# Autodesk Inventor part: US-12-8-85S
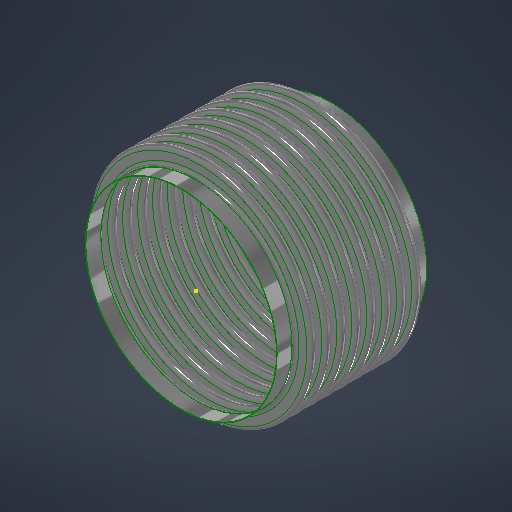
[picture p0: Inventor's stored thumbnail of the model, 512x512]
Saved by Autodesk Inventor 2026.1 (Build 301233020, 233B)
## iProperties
Category: 20 GA (0.036 THICK)
RuleStatus: InUse
Created: 2026-07
Part Number: US-12-8-85S
Project: =STOCK BELLOWS: <Stock Number><SFILL>
Material: ASTM A240-304
Description: =STOCK BELLOWS: <Stock Number>, <SID_> I.D., <SOD_> O.D., <SPLY_> PLY, <Category>, <SNET_CONS> CONS.<PITCH_><STANGENT_> TANGENT<SFILL>
Document SubType Name: Sheet Metal
Designer: LC
Stock Number: U.S-12-8-85S
Surface Area: 659.127 cm^2
Volume: 56.61 cm^3
Sheet Metal Rule: Default
Appearance: STAINLESS STEEL
NET_TUBE: 3.428
COUNTER: 1.500
PBAR: 1.214
PSET: 5.356
PLY: 2
CONS: 2
THK: 0.036
ID: 4.500
OD: 5.500
CONS_: 2
TANGENT: 0.500
PITCH: 0.375
BELLOWS_UPSET: 0.000
NET_CONS: 2
S_CONS: 0
Description_Units: 0
ID_M: 114.30 mm
OD_M: 139.70 mm
THK_M: 0.91 mm
ID_U: 4.500 in
OD_U: 5.500 in
THK_U: 0.036 in
TANGENT2: 0.500
d79: 1.000
d82: 1.000
d83: 26.000
d84: 24.000
d80: 2.571
d81: 10
SID: 2.375
SCONS_: 8
SPITCH: 0.250
SBELLOWS_UPSET: 0.000
SNET_CONS: 8
SS_CONS: 0
SCONS: 8
d174: 8
d177: 0.018
d178: 2.375
d179: 3.000
d180: 0.375
d181: 1.000
d182: 0.000
d190: 8
d191: 1
d192: 1
d193: 8
d194: 0
PART_NUMBER: U.S-12-8-85S
PRESSURE: 85
SIZE: 12.00
STANGENT_: 1.000
d214: 8
d217: 0.030
d218: 6.625
d219: 8.125
d220: 0.500
d221: 1.000
d222: 0.000
d230: 8
d231: 1
d232: 1
d233: 8
d234: 0
STANGENT: 4.000
SPLY_: 1
STHK_: 0.036
SID_: 12.750
SOD_: 14.875
SPITCH_: 1.000
STANGENT__: 1.000
SBELLOWS_UPSET_: 0.000
SDIFF_TAN: 1.000
TAN_TO_TAN: 0.750 in
d252: 2
d275: 2
d287: 0.050
d289: 0.500
d290: 0.000
d263: 2
d265: 1
d268: 2
d269: 0
d286: 2
d288: 1
d291: 2
d292: 0
SOD_NECK: 12 13/16
CFILL: .
SFILL: .
PITCH_: =, <SPITCH_> PITCH,
SREROLL: 0.750
MATTABLE: 20 GA (0.036 THICK)
MESH: ,
CSECT: 2
Author: LC
Keywords: 20 GA (0.036 THICK)
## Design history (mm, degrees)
sketch "Sketch2"
  geometry: L1 (0, -183.595)-(0, 600.956) reference; L2 (58.979, 0)-(57.15, 0); L3 (60.446, -1.467)-(66.554, -1.467); L4 (60.446, -3.296)-(66.554, -3.296); L5 (66.554, -8.058)-(60.446, -8.058); L6 (66.554, -6.229)-(60.446, -6.229); L7 (58.979, -9.525)-(57.15, -9.525); L8 (60.446, 0)-(60.446, -9.525); L9 (66.554, -4.762)-(69.85, -4.763); L10 (57.15, 0)-(57.15, -9.525); L11 (20.376, 102.841)-(20.376, 101.926); L12 (58.262, 488.877)-(58.262, 349.177); L13 (58.262, 479.352)-(58.262, 339.652); L14 (93.133, -58.817)-(93.133, -71.517); L15 (118.746, -66.401)-(118.746, -66.401); L16 (66.554, -6.229)-(66.554, -8.058); L17 (60.446, -6.229)-(60.446, -8.058); L18 (60.446, -7.144)-(66.554, -7.144); L19 (69.85, 0)-(69.85, -9.525); L20 (-66.554, -6.229)-(-66.554, -8.058); L21 (-66.554, -1.467)-(-60.446, -1.467); L22 (-66.554, -3.296)-(-60.446, -3.296); L23 (-60.446, -6.229)-(-66.554, -6.229); L24 (-66.554, -7.144)-(-60.446, -7.144); L25 (-60.446, -8.058)-(-66.554, -8.058); L26 (-60.446, -6.229)-(-60.446, -8.058); L27 (-57.15, -2.522)-(-57.15, -12.047); L28 (-60.446, -4.763)-(-57.15, -4.763); L29 (-66.554, 3.828)-(-66.554, -9.525); L30 (-68.021, 0)-(-69.85, 0); L31 (-69.85, 0)-(-69.85, -9.525); L32 (-68.021, -9.525)-(-69.85, -9.525); A1 r 1.467 centre (60.446, 0) between (58.979, 0) and (60.446, -1.467); A2 r 3.296 centre (60.446, 0) between (57.15, 0) and (60.446, -3.296); A3 r 3.296 centre (66.554, -4.762) between (66.554, -8.058) and (66.554, -1.467); A4 r 1.467 centre (66.554, -4.762) between (66.554, -6.229) and (66.554, -3.296); A5 r 1.467 centre (60.446, -9.525) between (60.446, -8.058) and (58.979, -9.525); A6 r 3.296 centre (60.446, -9.525) between (60.446, -6.229) and (57.15, -9.525); A7 r 2.381 centre (66.554, -4.762) between (66.554, -7.144) and (68.936, -4.762); A8 r 2.381 centre (60.446, -9.525) between (60.446, -7.144) and (58.064, -9.525); A9 r 1.467 centre (-66.554, -9.525) between (-66.554, -8.058) and (-68.021, -9.525); A10 r 1.467 centre (-60.446, -4.763) between (-60.446, -6.229) and (-60.446, -3.296); A11 r 2.381 centre (-60.446, -4.763) between (-60.446, -7.144) and (-58.064, -4.763); A12 r 3.296 centre (-60.446, -4.763) between (-60.446, -8.058) and (-60.446, -1.467); A13 r 2.381 centre (-66.554, -9.525) between (-66.554, -7.144) and (-68.936, -9.525); A14 r 3.296 centre (-66.554, -9.525) between (-66.554, -6.229) and (-69.85, -9.525); A15 r 1.467 centre (-66.554, 0) between (-68.021, 0) and (-66.554, -1.467); A16 r 3.296 centre (-66.554, 0) between (-69.85, 0) and (-66.554, -3.296); 10 further points
  constraints: 62 end point, 38 point on circle, 20 tangent, 16 centre point, 12 parallel, 9 midpoint, 7 vertical, 6 coincident, 6 concentric, 6 point on line, 4 equal radius, 4 perpendicular, 3 horizontal, 1 collinear, 1 horizontal alignment, 10 other
  dimensions: "THK" = 0.9144 distance of L11.start L11.end; "ID" = 114.3 distance of L11.end point (20.376, -12.374); "OD" = 139.7 distance of L12.start L12.end; "PITCH" = 9.525 distance of L12.start L13.start; "TANGENT" = 12.7 distance of L14.start L14.end; "BELLOWS_UPSET" = 0 distance of L15.start L15.end; "d43" = 114.3 diameter of L10 L1 (= ID); "d44" = 139.7 diameter of L9.end L1 (= OD); "d45" = 1.8288 distance between parallel lines of L5 L6 (computed from THK, PLY); "d46" = 3.29565 radius of A3 (computed from PITCH, THK, PLY); "UPSET_PITCH" = 9.525 distance of L2.end L7.end (derived); "SIDEWALL_ANGLE" = 0 deg angle of L3 L9 (derived); "CON_GAP" = 2.9337 distance of point (60.446, -6.229) point (60.446, -3.296) (derived); "TAN1" = 3.74046 dimension on A8 (derived); "TAN2" = 3.74046 dimension on A7 (derived); "LEG1" = 6.1087 distance of L18.start L18.end (derived); "d278" = 1.8288 distance between parallel lines of L25 L23 (derived); "d279" = 3.29565 radius of A12 (derived); "d280" = 9.525 distance of L30.end L31.end (derived); "d281" = 360 deg dimension on L21 L28 (derived); "d282" = 2.9337 distance of point (-66.554, -6.229) point (-66.554, -3.296) (derived); "d283" = 3.74046 dimension on A13 (derived); "d284" = 3.74046 dimension on A11 (derived); "d285" = 6.1087 distance of L24.start L24.end (derived); "d293" = 114.3 diameter of L27 L1 (derived); "d294" = 139.7 diameter of L31 L1 (derived)
  node "Sketch Rectangular Pattern1" dims "d31" = 25.4, "ID" = 114.3
  node "Sketch Rectangular Pattern2" dims "d39" = 25.4, "PITCH" = 9.525
revolve "CONS" stored, may be unused: angle "d48" = 90 deg
node "BELLOW MIDPLANE"
pattern_linear "Rectangular Pattern2" dims "d52" = 9.525 (= UPSET_PITCH)
sketch "Sketch5"
  geometry: C1 r 58.979 at (0, 0) reference; C2 r 57.15 at (0, 0) reference
extrude "TANGENT" new body sketch "Sketch5" distance "d53" = 12.7 (= TANGENT); taper "d54" = 0 deg
revolve "SAMETAN" stored, may be unused: angle "d65" = 90 deg
revolve "DIFFTAN" stored, may be unused: angle "d70" = 90 deg
sketch "Sketch9"
  geometry: L1 (58.391, 0)-(-58.391, 0) reference; L2 (0, -17.78)-(0, 17.78) reference; L3 (41.708, 0)-(-41.708, 0); L4 (41.708, -11.906)-(41.708, 11.906); L5 (29.008, -11.906)-(29.008, 11.906); L6 (15.418, 11.906)-(15.418, -11.906); L7 (-29.008, -11.906)-(-29.008, 11.906); L8 (-41.708, -11.906)-(-41.708, 11.906); L9 (40.914, -11.906)-(40.914, 11.906); L10 (41.708, -11.906)-(40.914, -11.906); L11 (41.708, 11.906)-(40.914, 11.906); L12 (15.815, 11.906)-(15.022, 11.906); L13 (15.022, 11.906)-(15.022, -11.906); L14 (15.022, -11.906)-(15.815, -11.906); L15 (15.815, -11.906)-(15.815, 11.906); L16 (-15.815, 11.906)-(-15.815, -11.906); L17 (-15.418, 11.906)-(-15.418, -11.906); L18 (-15.815, -11.906)-(-15.022, -11.906); L19 (-15.022, -11.906)-(-15.022, 11.906); L20 (-15.022, 11.906)-(-15.815, 11.906); L21 (-41.708, -11.906)-(-40.914, -11.906); L22 (-40.914, -11.906)-(-40.914, 11.906); L23 (-40.914, 11.906)-(-41.708, 11.906); L24 (-41.708, 11.906)-(-41.708, -11.906); L25 (41.708, -0.397)-(-41.708, -0.397); L26 (-41.708, -0.397)-(-41.708, 0.397); L27 (-41.708, 0.397)-(41.708, 0.397); L28 (41.708, 0.397)-(41.708, -0.397); L29 (-41.708, 11.906)-(41.708, 11.906); L30 (41.708, 11.906)-(41.708, 12.7); L31 (41.708, 12.7)-(-41.708, 12.7); L32 (-41.708, 12.7)-(-41.708, 11.906); L33 (41.708, -11.906)-(-41.708, -11.906); L34 (-41.708, -11.906)-(-41.708, -12.7); L35 (-41.708, -12.7)-(41.708, -12.7); L36 (41.708, -12.7)-(41.708, -11.906); 30 further points
  constraints: 68 end point, 13 midpoint, 13 parallel, 8 horizontal, 7 perpendicular, 6 equal length, 3 point on line, 2 vertical, 14 other
  dimensions: "d115" = 23.8125 distance of L4.start L4.end (derived); "d116" = 12.7 distance between parallel lines of L4 L5 (derived); "d117" = 13.58962 distance between parallel lines of L5 L6 (derived); "d125" = 44.42645 distance between parallel lines of L7 L6 (derived); "d127" = 12.7 distance between parallel lines of L8 L7 (derived); "d128" = 26.28962 distance between parallel lines of L6 L4 (derived); "d130" = 83.41607 distance between parallel lines of L8 L4 (derived); "RULER_THK" = 0.79375 distance between parallel lines of L4 L9; "d135" = 0.79375 distance of L13.end L14.end (derived); "d138" = 30.83684 distance of L13.end L16.end (derived); "d143" = 0.79375 distance of L22.end L8.end (derived); "d144" = 0.79375 distance between parallel lines of L27 L25 (derived)
extrude "RULER" join sketch "Sketch9" distance "d149" = 0.79375 (derived); taper "d150" = 0 deg
extrude "BARS" join sketch "Sketch9" distance "d151" = 0.79375 (derived); taper "d152" = 0 deg
pattern_linear "Rectangular Pattern4" dims "d155" = 30.83684 (derived)
sketch "Sketch13"
  geometry: L1 (93.149, -52.467)-(93.149, -77.867); L2 (162.839, 0)-(161.925, 0); L3 (162.839, -25.4)-(161.925, -25.4); L4 (182.105, -19.507)-(168.732, -19.507); L5 (182.105, -18.593)-(168.732, -18.593); L6 (182.105, -12.7)-(188.912, -12.7); L7 (168.732, -5.893)-(182.105, -5.893); L8 (168.732, 0)-(168.732, -25.4); L9 (161.925, 0)-(161.925, -25.4); L10 (58.254, -267.831)-(58.254, -645.656); L11 (58.254, -293.231)-(58.254, -671.056); L12 (58.254, -344.031)-(58.254, -721.856); L13 (58.254, -369.431)-(58.254, -747.256); L14 (58.254, -394.831)-(58.254, -772.656); L15 (58.254, -420.231)-(58.254, -798.056); L16 (58.254, -445.631)-(58.254, -823.456); L17 (58.254, -318.631)-(58.254, -696.456); L18 (20.376, 102.841)-(20.376, 101.926); L19 (168.732, -6.807)-(182.105, -6.807); L20 (0, -960.455)-(0, 280.056) reference; L21 (-31.75, 0)-(190.5, 0) reference; A1 r 5.893 centre (168.732, 0) between (162.839, 0) and (168.732, -5.893); A2 r 5.893 centre (168.732, -25.4) between (168.732, -19.507) and (162.839, -25.4); A3 r 6.807 centre (168.732, -25.4) between (168.732, -18.593) and (161.925, -25.4); A4 r 5.893 centre (182.105, -12.7) between (182.105, -18.593) and (182.105, -6.807); A5 r 6.807 centre (182.105, -12.7) between (182.105, -19.507) and (182.105, -5.893); A6 r 6.807 centre (168.732, 0) between (161.925, 0) and (168.732, -6.807); 6 further points; 1 other entity
  constraints: 38 end point, 15 point on circle, 9 tangent, 6 centre point, 6 parallel, 5 vertical alignment, 4 point on line, 4 vertical, 3 coincident, 3 concentric, 2 collinear, 2 equal radius, 1 horizontal, 1 perpendicular, 23 other
  dimensions: "SBELLOWS_UPSET_" = 0 distance of point (118.762, -66.401) point (118.762, -66.401); "STOTAL_THK_BELLOW__" = 0.9144 distance between parallel lines of L4 L5 (derived); "d224" = 6.8072 radius of A5 (derived); "d225" = 25.4 distance of L2.end L3.end (derived); "SSIDEWALL_ANGLE_" = 0 deg angle of L7 L6 (derived); "SSCON_GAP_" = 11.7856 distance of point (168.732, -18.593) point (168.732, -6.807) (derived); "d235" = 323.85 diameter of L9 L20 (derived); "d236" = 377.825 diameter of L6.end L20 (derived)
  node "Sketch Rectangular Pattern4" dims "d228" = 25.4
  node "Sketch Rectangular Pattern5" dims "d229" = 25.4
revolve "SBELLOW" stored, may be unused: angle "d197" = 90 deg
pattern_linear "Rectangular Pattern5" dims "d204" = 25.4 (derived)
revolve "STANGENT" stored, may be unused: angle "d240" = 90 deg
revolve "SSAMETAN" stored, may be unused: angle "d241" = 90 deg
revolve "SDIFFTAN" stored, may be unused: angle "d246" = 90 deg
revolve "INVCON" stored, may be unused: angle "d295" = 90 deg
pattern_linear "Rectangular Pattern6" dims "d298" = 9.525 (derived)
revolve "INVTANGENT" stored, may be unused: angle "d302" = 90 deg
revolve "INVSAMETAN" stored, may be unused: angle "d307" = 90 deg
revolve "INVDIFFTAN" stored, may be unused: angle "d312" = 90 deg
sketch "ID BELLOW MOUNT CALC"
  geometry: L1 (44.45, 0)-(38.1, 0); L2 (38.1, 0)-(38.1, 12.7); L3 (38.1, 12.7)-(44.45, 12.7); L4 (44.45, 12.7)-(44.45, 0); L5 (36.513, 12.7)-(34.684, 12.7); L6 (34.684, 12.7)-(34.684, 0); L7 (34.684, 0)-(36.513, 0); L8 (36.513, 0)-(36.513, 12.7); L9 (0, -2.54)-(0, 15.24) reference; L10 (-8.89, 0)-(53.34, 0) reference; 1 further point
  constraints: 16 end point, 5 parallel, 2 collinear, 2 horizontal, 2 perpendicular
  dimensions: "d314" = 12.7 distance of L5.end L6.end (derived); "d315" = 1.8288 distance of L5.start L5.end (derived); "IG" = 1.5875 distance between parallel lines of L2 L8; "PIPE_OD" = 88.9 diameter of L4 L9; "PIPE_WALL" = 6.35 distance of L2.end L3.end; "ID_MT_BELLOW" = 69.3674 diameter of L6 L9 (derived)
revolve "CFILL" stored, may be unused: angle "d320" = 90 deg
pattern_linear "Rectangular Pattern7" dims "d323" = 9.525 (derived)
revolve "SFILL" stored, may be unused: angle "d324" = 90 deg
pattern_linear "Rectangular Pattern8" dims "d327" = 25.4 (derived)
node "STOCK BELLOW MIDPLANE"
sketch "Sketch21"
  geometry: L1 (0, -100.013)-(0, 100.013) reference; L2 (-100.013, 0)-(100.013, 0) reference; L3 (-0.099, 71.437)-(0.099, 71.437); L4 (0.099, 71.437)-(0.099, 55.562); L5 (0.099, 55.562)-(-0.099, 55.562); L6 (-0.099, 55.562)-(-0.099, 71.437); C1 r 55.562 at (0, 0); C2 r 71.437 at (0, 0); 3 further points
  constraints: 8 end point, 2 centre point, 2 coincident, 2 parallel, 2 tangent, 1 horizontal, 1 perpendicular, 1 other
  dimensions: "d329" = 111.125 diameter of C1 (derived); "d330" = 142.875 diameter of C2 (derived); "d331" = 0.19844 distance of L3.start L3.end
extrude "CLAMSHELL" cut sketch "Sketch21" extent not by distance; stored distance "d332" = 0; taper "d333" = 0 deg
pattern_circular "Circular Pattern1" dims angle "d335" = 180 deg (derived)
node "BELLOW"
sketch "Sketch6"
  geometry: L1 (-19.05, 58.979)-(-6.35, 58.979); L2 (-6.35, 58.979)-(-6.35, 57.15); L3 (-6.35, 57.15)-(-19.05, 57.15); L4 (-19.05, 57.15)-(-19.05, 58.979); L5 (2.54, 0)-(-59.69, 0) reference; L6 (-38.1, -108.388)-(-38.1, 156.601) reference; 1 further point
  constraints: 8 end point, 2 parallel, 1 horizontal, 1 perpendicular
  dimensions: "d61" = 12.7 distance of L2.end L3.end (derived); "d62" = 1.8288 distance of L1.end L2.end (derived); "d63" = 114.3 diameter of L3 L5 (derived); "d64" = 19.05 distance between parallel lines of L4 L6 (derived)
sketch "Sketch12"
  geometry: 1 further point
sketch "Sketch14"
  geometry: L1 (-25.4, 162.839)-(0, 162.839); L2 (0, 162.839)-(0, 161.925); L3 (0, 161.925)-(-25.4, 161.925); L4 (-25.4, 161.925)-(-25.4, 162.839); L5 (5.08, 0)-(-30.48, 0) reference; L6 (0, -27.488)-(0, 164.927) reference; 1 further point
  constraints: 8 end point, 2 parallel, 1 collinear, 1 horizontal, 1 perpendicular
  dimensions: "d237" = 0.9144 distance of L3.end L1.start (derived); "d238" = 323.85 diameter of L3 L5 (derived); "d239" = 25.4 distance of L1.start L1.end (derived); "SOD_NECK" = 325.6788 diameter of L1 L5 (derived)
sketch "Sketch15"
  geometry: L1 (-27.488, 0)-(164.927, 0) reference; L2 (161.925, -203.2)-(162.839, -203.2); L3 (162.839, -203.2)-(162.839, -228.6); L4 (162.839, -228.6)-(161.925, -228.6); L5 (161.925, -228.6)-(161.925, -203.2); L6 (0, -276.86)-(0, 60.96) reference; 1 further point
  constraints: 8 end point, 2 parallel, 1 horizontal, 1 perpendicular
  dimensions: "d205" = 25.4 distance of L4.end L2.start (derived); "d206" = 0.9144 distance of L3.end L4.end (derived); "d207" = 323.85 diameter of L5 L6 (derived); "d208" = 203.2 distance between parallel lines of L1 L2 (derived)
node "TANGENT_"
node "SAME_TAN"
sketch "Sketch8"
  geometry: L1 (58.979, -19.05)-(57.15, -19.05); L2 (57.15, -19.05)-(57.15, -31.75); L3 (57.15, -31.75)-(58.979, -31.75); L4 (58.979, -31.75)-(58.979, -19.05); L5 (0, -40.64)-(0, 21.59) reference; L6 (-108.388, 0)-(156.601, 0) reference; 1 further point
  constraints: 8 end point, 2 parallel, 1 horizontal, 1 perpendicular
  dimensions: "d66" = 114.3 diameter of L2 L5 (derived); "TOTAL_THK_BELLOW" = 1.8288 distance of L2.end L3.end (derived); "d68" = 19.05 distance between parallel lines of L1 L6 (derived); "d69" = 12.7 distance of L1.end L2.end (derived)
node "DIFF_TAN"
node "Sketch Rectangular Pattern3" dims "d138" = 30.83684 (derived), "d141" = 25.4
node "SBELLOW_"
node "STANGENT_"
node "SSAME_TAN"
sketch "Sketch16"
  geometry: L1 (162.839, -203.2)-(161.925, -203.2); L2 (161.925, -203.2)-(161.925, -228.6); L3 (161.925, -228.6)-(162.839, -228.6); L4 (162.839, -228.6)-(162.839, -203.2); L5 (0, -276.86)-(0, 60.96) reference; L6 (-27.488, 0)-(164.927, 0) reference; 1 further point
  constraints: 8 end point, 2 parallel, 1 horizontal, 1 perpendicular
  dimensions: "SDIFF_TAN" = 25.4 distance of L3.end L1.start; "d243" = 0.9144 distance of L2.end L3.end (derived); "d244" = 203.2 distance between parallel lines of L1 L6 (derived); "d245" = 323.85 diameter of L2 L5 (derived)
node "SDIFF_TAN"
body "Solid15"
sketch "Sketch17"
  geometry: L1 (69.85, 12.7)-(68.021, 12.7); L2 (68.021, 12.7)-(68.021, 0); L3 (68.021, 0)-(69.85, 0); L4 (69.85, 0)-(69.85, 12.7); L5 (0, -2.54)-(0, 15.24) reference; L6 (-13.97, 0)-(83.82, 0) reference; 2 further points
  constraints: 8 end point, 2 parallel, 1 horizontal, 1 midpoint, 1 perpendicular, 1 point on line
  dimensions: "INVTANGENT" = 12.7 distance of L3.end L1.start (derived); "d300" = 1.8288 distance of L1.start L1.end (derived); "d301" = 139.7 diameter of L4 L5 (derived)
body "Solid16"
sketch "Sketch18"
  geometry: L1 (69.85, -19.05)-(68.021, -19.05); L2 (68.021, -19.05)-(68.021, -31.75); L3 (68.021, -31.75)-(69.85, -31.75); L4 (69.85, -31.75)-(69.85, -19.05); L5 (-13.97, 0)-(83.82, 0) reference; L6 (0, -40.64)-(0, 21.59) reference; 1 further point
  constraints: 8 end point, 2 parallel, 1 horizontal, 1 perpendicular
  dimensions: "d303" = 19.05 distance between parallel lines of L1 L5 (derived); "d304" = 12.7 distance of L3.end L1.start (derived); "d305" = 1.8288 distance of L2.end L3.end (derived); "d306" = 139.7 diameter of L4 L6 (derived)
body "Solid17"
sketch "Sketch19"
  geometry: L1 (69.85, -19.05)-(68.021, -19.05); L2 (68.021, -19.05)-(68.021, -31.75); L3 (68.021, -31.75)-(69.85, -31.75); L4 (69.85, -31.75)-(69.85, -19.05); L5 (0, -40.64)-(0, 21.59) reference; L6 (-13.97, 0)-(83.82, 0) reference; 1 further point
  constraints: 8 end point, 2 parallel, 1 horizontal, 1 perpendicular
  dimensions: "d308" = 12.7 distance of L1.end L2.end (derived); "d309" = 139.7 diameter of L4 L5 (derived); "d310" = 1.8288 distance of L2.end L3.end (derived); "d311" = 19.05 distance between parallel lines of L1 L6 (derived)
body "Solid18"
body "Solid19"
body "Solid20"
other parameters: "BMPL" = -101.6, "PSET" = 136.0424 (computed from OD, THK, PLY) [user parameter], "PBAR" = 30.83684 (= 0.570796 x PITCH + OD - ID) [user parameter; used in 1 equation term], "COUNTER" = 15 [user parameter], "NET_TUBE" = 87.07367 (computed from CONS_, PBAR, TANGENT) [user parameter], "S_CONS" = 0 [user parameter; used in 1 equation term], "ID_M" = 114.3 (= ID) [user parameter], "OD_M" = 139.7 (= OD) [user parameter], "THK_M" = 0.9144 (= THK) [user parameter], "ID_U" = 114.3 (= ID) [user parameter], "OD_U" = 139.7 (= OD) [user parameter], "THK_U" = 0.9144 (= THK) [user parameter], "D_UNITS" = 0 [user parameter], "TANGENT2" = 12.7 [user parameter], "TAN_TO_TAN" = 19.05 [user parameter], "OD_NECK" = 117.9576 [user parameter], "d79" = 25.4, "d80" = 65.29823 [user parameter], "d82" = 25.4, "d83" = 660.4, "d84" = 609.6, "sa_0" = 4, "FRAME_THK" = 0.79375 [user parameter], "CON_FLAT" = 13.58962 [user parameter], "SID" = 60.325 [user parameter], "SPITCH" = 6.35 [user parameter], "STANGENT_" = 25.4 [user parameter], "SBELLOWS_UPSET" = 0 [user parameter], "SS_CONS" = 0 [user parameter], "STAN_TO_TAN_" = 203.2 [user parameter], "d100" = 0.9144 [user parameter], "d191" = 25.4 [user parameter], "d194" = 0 [user parameter], "STANGENT" = 101.6 [user parameter], "d234" = 0 [user parameter], "SUPSET_PITCH_" = 25.4 [user parameter], "d269" = 0 [user parameter], "d287" = 1.27, "d289" = 12.7, "d290" = 0, "d292" = 0 [user parameter], "Thickness" = 3.048 (derived), "KFactor" = 4.4, "BendRadius" = 3.048 (derived), "BendReliefWidth" = 3.048 (derived), "BendReliefDepth" = 1.524 (derived), "CornerReliefSize" = 12.192 (derived), "SeamGap" = 0.00508, "MinimumRemnant" = 6.096 (derived), "TransitionRadius" = 3.048 (derived), "JacobiRadiusSize" = 3.048 (derived), "GapSize" = 3.048 (derived), "SREROLL" = 19.05 [user parameter], "CUR_STK_PITCH" = 25.4 [user parameter], "d328" = -101.6 (derived), "CSECTDEG" = 180 deg [user parameter]
